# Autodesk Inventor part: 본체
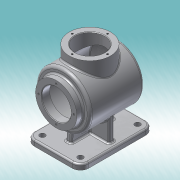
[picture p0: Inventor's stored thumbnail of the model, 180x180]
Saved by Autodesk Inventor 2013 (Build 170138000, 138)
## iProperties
Created: 2016-09
Part Number: 본체
Material: 알루미늄 6061
Document SubType Name: Modeling
Designer: dgall
Density: 2.71 g/cm^3
Mass: 972.332 g
Surface Area: 1283.36 cm^2
Volume: 358.794 cm^3
Author: dgall
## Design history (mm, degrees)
sketch "스케치1"
  geometry: L1 (0, 0)-(122, 0); L2 (0, 27)-(0, 38); L3 (0, 38)-(12, 38); L4 (12, 38)-(12, 50); L5 (12, 50)-(110.562, 50); L6 (108.661, 47)-(15, 47); L7 (15, 47)-(15, 27); L8 (0, 27)-(15, 27); A1 r 115 centre (7, 0) between (122, 0) and (110.562, 50); A2 r 112 centre (7, 0) between (119, 0) and (108.661, 47)
  constraints: 16 end point, 4 point on circle, 2 centre point, 2 parallel, 2 perpendicular, 2 point on line, 1 horizontal, 1 vertical alignment, 2 other
  dimensions: "d0" = 115 radius of A1; "d2" = 54 diameter of L8 L1; "d3" = 76 diameter of L3 L1; "d4" = 100 diameter of L5 L1; "d5" = 3 distance between parallel lines of L6 L5; "d6" = 12 distance of L2.end L3.end; "d7" = 110 distance from line of L1.end L4
revolve "회전1" sketch "스케치1" stored, may be unused: angle "d8" = 90 deg
fillet "모깎기1" dims "d9" = 5
node "작업 평면1"
fillet "모깎기2" dims "d10" = 2
node "작업축1"
node "작업 평면2"
sketch "스케치2"
  geometry: L1 (5.313, -50)-(-129.687, -50); L2 (-129.687, -50)-(-129.687, 50); L3 (-129.687, 50)-(5.313, 50); L4 (5.313, 50)-(5.313, -50); L5 (-17, 50)-(-107.374, 50) reference; 4 further points
  constraints: 8 end point, 3 midpoint, 2 parallel, 1 horizontal, 1 horizontal alignment, 1 perpendicular
  dimensions: "d12" = 135 distance of L2.end L3.end; "d14" = 100 distance of L1.end L2.end; "d15" = 67.5 distance from line of L2 point (-62.187, 50)
extrude "돌출1" join sketch "스케치2" distance "d16" = 10; taper "d17" = 0 deg
node "작업 평면3"
sketch "스케치3"
  geometry: L1 (22.313, 32)-(112.687, 32) reference; L2 (29.573, 33.7)-(27.5, 10); L3 (0, 0)-(0, 10) reference; L4 (135, 10)-(0, 10) reference; L5 (107.5, 10)-(27.5, 10); L6 (107.5, 10)-(105.427, 33.7); L7 (105.427, 33.7)-(29.573, 33.7); L8 (22.313, 132)-(112.687, 132) reference; 4 further points
  constraints: 8 end point, 4 midpoint, 1 coincident, 1 collinear, 1 parallel
  dimensions: "d21" = 80 distance of L2.end L5.start; "d85" = 95 deg angle of L4 L2; "d87" = 95 deg angle of L4 L6; "d89" = 23.7 distance between parallel lines of L4 L7
extrude "돌출2" join sketch "스케치3" stored distance "d24" = 10; taper "d25" = 0 deg
node "작업 평면4"
sketch "스케치4"
  geometry: L1 (10, 0)-(10, 100) reference; L2 (52, 90)-(10, 90); L3 (52, 10)-(10, 10); L4 (10, 10)-(10, 90); A1 r 50 centre (82, 50) between (52, 90) and (52, 10) reference; A2 r 53.268 centre (87.177, 50) between (52, 90) and (52, 10); 1 further point
  constraints: 6 end point, 4 point on circle, 2 perpendicular, 2 point on line, 1 centre point, 1 collinear, 1 parallel
  dimensions: "d26" = 80 distance between parallel lines of L3 L2; "d27" = 53.26766 radius of A2
extrude "돌출3" join sketch "스케치4" stored distance "d28" = 10; taper "d29" = 0 deg
node "작업 평면5"
sketch "스케치5"
  geometry: L1 (-5.313, 50)-(-5.313, -50) reference; L2 (12, -45)-(12, 45) reference; C1 r 38 at (62, 0); 1 further point
  constraints: 1 centre point, 1 horizontal alignment
  dimensions: "d32" = 76 diameter of C1; "d83" = 50 distance from line of L2 C1.centre
extrude "돌출4" join sketch "스케치5" stored distance "d33" = 10; taper "d34" = 0 deg
sketch "스케치6"
  geometry: C1 r 38 at (0, 0) reference; 2 further points
  constraints: 1 coincident
hole "구멍1" sketch "스케치6" at (0, 0) diameter "d35" = 54; stored, may be unused: countersink angle "d39" = 90 deg, drill point angle "d41" = 118 deg; dims "d36" = 6, "d37" = 4, "d38" = 2, "d40" = 50
chamfer "모따기1" distance "d42" = 1; stored, may be unused: second distance "d43" = 2, angle "d44" = 45 deg
sketch "스케치7"
  geometry: C1 r 38 at (0, 0) reference; 2 further points
  constraints: 1 vertical alignment
  dimensions: "d45" = 32.5 distance of C1.centre point (0, 32.5)
hole "구멍2" sketch "스케치7" at (0, 32.5) diameter "d46" = 3.242; stored, may be unused: countersink angle "d50" = 90 deg, drill point angle "d52" = 118 deg; dims "d47" = 8, "d48" = 4, "d49" = 2, "d51" = 10
sketch "스케치8"
  geometry: C1 r 38 at (0, 0) reference; 1 further point
  constraints: 1 vertical alignment
  dimensions: "d56" = 32.5 distance of C1.centre point (0, 32.5)
hole "구멍3" sketch "스케치8" at (0, 32.5) diameter "d57" = 3.242; stored, may be unused: countersink angle "d61" = 90 deg, drill point angle "d63" = 118 deg; dims "d58" = 8, "d59" = 4, "d60" = 2, "d62" = 10
fillet "모깎기3" dims "d67" = 15
fillet "모깎기4" dims "d68" = 3
fillet "모깎기5" dims "d69" = 3
fillet "모깎기6" dims "d70" = 3
fillet "모깎기7" dims "d71" = 3
fillet "모깎기8" dims "d72" = 3
sketch "스케치9"
  geometry: A1 r 12 centre (114.687, -35) between (114.687, -47) and (126.687, -35) reference; A2 r 12 centre (114.687, 35) between (126.687, 35) and (114.687, 47) reference; A3 r 12 centre (9.687, 35) between (9.687, 47) and (-2.313, 35) reference; A4 r 12 centre (9.687, -35) between (-2.313, -35) and (9.687, -47) reference; 5 further points
  constraints: 4 coincident
hole "구멍4" sketch "스케치9" at (9.687, 35), (114.687, 35), (114.687, -35), (9.687, -35) diameter "d73" = 10; stored, may be unused: countersink angle "d77" = 90 deg, drill point angle "d79" = 118 deg; dims "d74" = 8, "d75" = 4, "d76" = 2, "d78" = 10
node "작업 평면6"
sketch "스케치10"
  geometry: 2 further points
  constraints: 1 coincident, 1 other
feature "엠보싱1" sketch "스케치10" dims "d0" = 115, "d2" = 54, "d3" = 76, "d4" = 100, "d5" = 3, "d6" = 12, "d7" = 110, "d11" = -82, "d80" = 0.5, "d81" = 0
fillet "모깎기9" dims "d82" = 3
node "솔리드1"
pattern_circular "원형 패턴1" dims angle "d54" = 360 deg
pattern_circular "원형 패턴2" dims angle "d65" = 360 deg
other parameters: "d30" = -147
